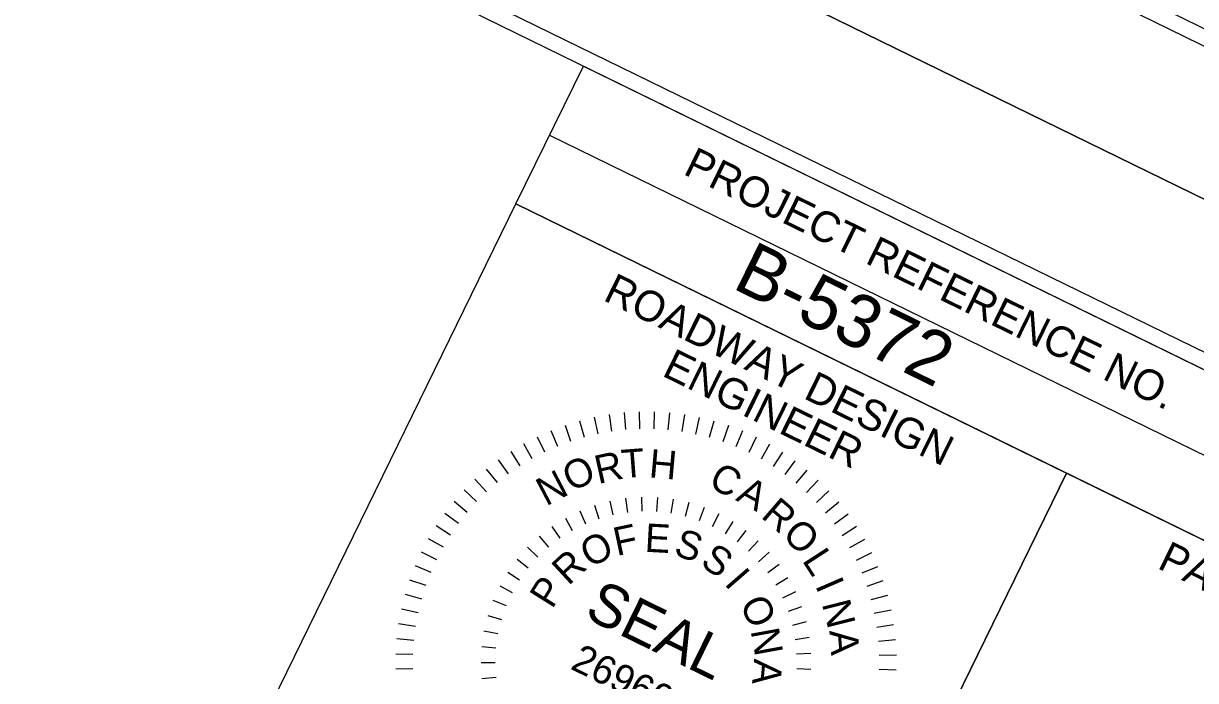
# Model space of a CAD drawing. Extents: x 1518247 to 1523638, y 635234 to 639927.
# Drawn here: x 1521174.1 to 1521365.4, y 636194.9 to 636302.2 of the extents above; entities that cross this region are included whole.
import ezdxf

# ---------------------------------------------------------------- set-up
doc = ezdxf.new("R2010")
doc.units = 0
for name, color, linetype in [('Default', 7, 'Continuous'), ('DTM TIN Hull White', 7, 'Continuous'), ('Prop Dimension Text', 7, 'Continuous'), ('Sheet Cutting Line CELL', 7, 'Continuous'), ('Sheet Plot Border Inside CELL', 7, 'Continuous'), ('Sheet Plot Border Outside CELL', 7, 'Continuous'), ('Sheet Typical CELL', 7, 'Continuous')]:
    doc.layers.add(name, color=color, linetype=linetype)

msp = doc.modelspace()

# ---------------------------------------------------------------- linework, layer by layer
at = {"layer": 'Default'}
msp.add_lwpolyline([(1521471.45, 636222.33), (1519958.68, 636962.19), (1520441.97, 637950.34), (1521954.73, 637210.48)], close=True, dxfattribs=at)
at = {"layer": 'DTM TIN Hull White'}
for p, q in [((1521264.85, 636237.33), (1521265.59, 636234.65)), ((1521267.25, 636237.92), (1521267.82, 636235.19)), ((1521269.68, 636238.35), (1521270.09, 636235.6)), ((1521272.13, 636238.65), (1521272.37, 636235.87)), ((1521274.59, 636238.79), (1521274.67, 636236)), ((1521277.06, 636238.78), (1521276.97, 636236)), ((1521279.53, 636238.63), (1521279.27, 636235.85)), ((1521281.98, 636238.33), (1521281.55, 636235.57)), ((1521284.41, 636237.87), (1521283.81, 636235.15)), ((1521286.8, 636237.27), (1521286.04, 636234.59)), ((1521260.18, 636235.73), (1521261.24, 636233.16)), ((1521262.49, 636236.6), (1521263.39, 636233.97)), ((1521289.15, 636236.53), (1521288.24, 636233.9)), ((1521291.46, 636235.65), (1521290.39, 636233.08)), ((1521255.73, 636233.59), (1521257.09, 636231.16)), ((1521257.92, 636234.72), (1521259.13, 636232.22)), ((1521293.71, 636234.63), (1521292.48, 636232.13)), ((1521295.89, 636233.48), (1521294.52, 636231.05)), ((1521253.62, 636232.32), (1521255.12, 636229.97)), ((1521298, 636232.19), (1521296.49, 636229.86)), ((1521249.63, 636229.4), (1521251.41, 636227.25)), ((1521251.58, 636230.92), (1521253.23, 636228.67)), ((1521300.03, 636230.79), (1521298.38, 636228.55)), ((1521301.97, 636229.26), (1521300.18, 636227.12)), ((1521247.78, 636227.77), (1521249.68, 636225.73)), ((1521303.82, 636227.62), (1521301.9, 636225.59)), ((1521246.03, 636226.03), (1521248.06, 636224.11)), ((1521305.56, 636225.87), (1521303.52, 636223.96)), ((1521244.39, 636224.18), (1521246.52, 636222.39)), ((1521267.31, 636223.52), (1521268.03, 636221.31)), ((1521269.81, 636224.21), (1521270.32, 636221.95)), ((1521272.38, 636224.66), (1521272.67, 636222.35)), ((1521274.98, 636224.86), (1521275.04, 636222.54)), ((1521277.58, 636224.81), (1521277.42, 636222.49)), ((1521280.17, 636224.5), (1521279.78, 636222.21)), ((1521282.71, 636223.95), (1521282.1, 636221.7)), ((1521307.19, 636224.01), (1521305.04, 636222.23)), ((1521242.86, 636222.24), (1521245.1, 636220.59)), ((1521264.88, 636222.59), (1521265.81, 636220.47)), ((1521285.18, 636223.15), (1521284.37, 636220.98)), ((1521287.58, 636222.12), (1521286.55, 636220.03)), ((1521286.55, 636220.03), (1521287.58, 636222.12)), ((1521308.71, 636222.07), (1521306.46, 636220.42)), ((1521241.45, 636220.21), (1521243.79, 636218.7)), ((1521260.34, 636220.05), (1521261.66, 636218.14)), ((1521262.55, 636221.43), (1521263.68, 636219.4)), ((1521289.86, 636220.86), (1521288.64, 636218.88)), ((1521310.1, 636220.03), (1521307.76, 636218.52)), ((1521240.17, 636218.1), (1521242.59, 636216.73)), ((1521258.28, 636218.46), (1521259.78, 636216.69)), ((1521292, 636219.39), (1521290.6, 636217.54)), ((1521311.38, 636217.91), (1521308.95, 636216.55)), ((1521239.02, 636215.92), (1521241.52, 636214.69)), ((1521256.38, 636216.68), (1521258.05, 636215.07)), ((1521294, 636217.72), (1521292.42, 636216.01)), ((1521295.82, 636215.86), (1521294.09, 636214.31)), ((1521254.66, 636214.73), (1521256.47, 636213.28)), ((1521312.51, 636215.73), (1521310.01, 636214.51)), ((1521238, 636213.67), (1521240.57, 636212.6)), ((1521253.13, 636212.62), (1521255.08, 636211.35)), ((1521297.46, 636213.84), (1521295.59, 636212.46)), ((1521313.52, 636213.47), (1521310.95, 636212.41)), ((1521237.12, 636211.36), (1521239.74, 636210.45)), ((1521251.82, 636210.37), (1521253.88, 636209.29)), ((1521298.89, 636211.66), (1521296.9, 636210.48)), ((1521314.39, 636211.16), (1521311.76, 636210.26)), ((1521236.37, 636209.01), (1521239.05, 636208.25)), ((1521300.11, 636209.36), (1521298.01, 636208.37)), ((1521315.12, 636208.8), (1521312.44, 636208.06)), ((1521235.78, 636206.62), (1521238.5, 636206.02)), ((1521250.73, 636208), (1521252.88, 636207.13)), ((1521301.1, 636206.95), (1521298.91, 636206.18)), ((1521315.71, 636206.4), (1521312.98, 636205.82)), ((1521249.88, 636205.54), (1521252.1, 636204.89)), ((1521301.85, 636204.46), (1521299.6, 636203.9)), ((1521235.32, 636204.19), (1521238.08, 636203.76)), ((1521249.26, 636203.01), (1521251.54, 636202.58)), ((1521316.14, 636203.97), (1521313.39, 636203.56)), ((1521235.02, 636201.74), (1521237.8, 636201.48)), ((1521302.36, 636201.91), (1521300.07, 636201.56)), ((1521316.44, 636201.52), (1521313.66, 636201.27)), ((1521234.87, 636199.27), (1521237.65, 636199.18)), ((1521248.89, 636200.44), (1521251.21, 636200.22)), ((1521302.62, 636199.32), (1521300.3, 636199.2)), ((1521316.58, 636199.05), (1521313.79, 636198.98)), ((1521234.86, 636196.8), (1521237.64, 636196.88)), ((1521248.78, 636197.84), (1521251.1, 636197.85)), ((1521302.63, 636196.72), (1521300.31, 636196.82)), ((1521248.91, 636195.24), (1521251.22, 636195.47)), ((1521316.57, 636196.58), (1521313.79, 636196.68))]:
    msp.add_line(p, q, dxfattribs=at)
at = {"layer": 'Sheet Cutting Line CELL'}
for p, q in [((1519958.68, 636962.19), (1521471.45, 636222.33)), ((1521471.45, 636222.33), (1519958.68, 636962.19))]:
    msp.add_line(p, q, dxfattribs=at)
at = {"layer": 'Sheet Plot Border Inside CELL'}
for points in [[(1521940.83, 637192.29), (1520443.78, 637924.46), (1519980.23, 636976.65), (1521477.27, 636244.48)], [(1521457.54, 636204.14), (1519960.5, 636936.31), (1519496.94, 635988.5), (1520993.99, 635256.33)]]:
    msp.add_lwpolyline(points, close=True, dxfattribs=at)
at = {"layer": 'Sheet Plot Border Outside CELL'}
for points in [[(1521954.73, 637210.48), (1520441.97, 637950.34), (1519958.68, 636962.19), (1521471.45, 636222.33)], [(1521471.45, 636222.33), (1519958.68, 636962.19), (1519475.4, 635974.04), (1520988.17, 635234.18)]]:
    msp.add_lwpolyline(points, close=True, dxfattribs=at)
at = {"layer": 'Sheet Typical CELL'}
for p, q in [((1521259.97, 636283.96), (1521439.68, 636196.07)), ((1521344.36, 636228.77), (1521294.95, 636127.76))]:
    msp.add_line(p, q, dxfattribs=at)
for points in [[(1521928.48, 637195.49), (1520581, 637854.51), (1520119.69, 636911.28), (1521467.16, 636252.26)], [(1521445.2, 636207.34), (1520097.72, 636866.36), (1519636.4, 635923.13), (1520983.88, 635264.11)], [(1521265.49, 636295.23), (1521445.2, 636207.34), (1521434.19, 636184.84), (1521254.48, 636272.73)], [(1521254.48, 636272.73), (1521344.36, 636228.77), (1521294.93, 636127.71), (1521205.05, 636171.67)], [(1521344.36, 636228.77), (1521434.19, 636184.84), (1521384.76, 636083.78), (1521294.93, 636127.71)]]:
    msp.add_lwpolyline(points, close=True, dxfattribs=at)

# ---------------------------------------------------------------- texts
at = {"layer": 'DTM TIN Hull White'}
for s, height, rotation, p in [('O', 4.64, 25.602, (1521263.51, 636225.65)), ('R', 4.64, 12.5453, (1521267.9, 636226.97)), ('T', 4.64, 4.3843, (1521271.85, 636227.93)), ('H', 4.64, 354.9524, (1521276.09, 636228.1)), ('N', 4.64, 27.5614, (1521259.39, 636223.3)), ('C', 4.64, 331.2417, (1521285.69, 636226.71)), ('A', 4.64, 331.2417, (1521290.21, 636224.4)), ('R', 4.64, 319.2324, (1521294.32, 636221.62)), ('F', 4.64, 12.1253, (1521270.94, 636215.22)), ('E', 4.64, 356.8291, (1521275.43, 636215.94)), ('O', 4.64, 316.1756, (1521297.77, 636218.44)), ('O', 4.64, 27.4216, (1521266.53, 636213.22)), ('S', 4.64, 341.5328, (1521280.05, 636215.45)), ('R', 4.64, 42.7178, (1521263.04, 636210.28)), ('S', 4.64, 326.2366, (1521284.38, 636213.76)), ('L', 4.64, 303.0393, (1521301.1, 636214.51)), ('I', 4.64, 310.9403, (1521288.37, 636210.69)), ('P', 4.64, 58.0141, (1521260.39, 636206.46)), ('SEAL', 6.965, 333.8847, (1521265.43, 636205.3)), ('I', 4.64, 293.4638, (1521303.27, 636210.44)), ('O', 4.64, 295.6441, (1521290.93, 636207.42)), ('N', 4.64, 284.1693, (1521304.4, 636207.45)), ('N', 4.64, 280.3478, (1521292.77, 636203.06)), ('A', 4.64, 274.4018, (1521305.64, 636203.03)), ('26960', 4.64, 333.8847, (1521263.19, 636196.89)), ('A', 4.64, 265.0516, (1521293.38, 636198.52))]:
    msp.add_text(s, height=height, rotation=rotation, dxfattribs=at).set_placement(p)
at = {"layer": 'Prop Dimension Text'}
msp.add_text('B-5372', height=8.643, rotation=333.8962, dxfattribs=at).set_placement((1521289.58, 636259.06))
at = {"layer": 'Sheet Typical CELL'}
for s, height, p in [('PROJECT REFERENCE NO.', 5.0001, (1521281.61, 636277.67)), ('ROADWAY DESIGN', 5.0001, (1521268.53, 636257.07)), ('ENGINEER', 5, (1521278.14, 636244.74)), ('PAVEMENT DESIGN', 5.0001, (1521359.01, 636213.32))]:
    msp.add_text(s, height=height, rotation=333.9377, dxfattribs=at).set_placement(p)

doc.saveas('drawing.dxf')
